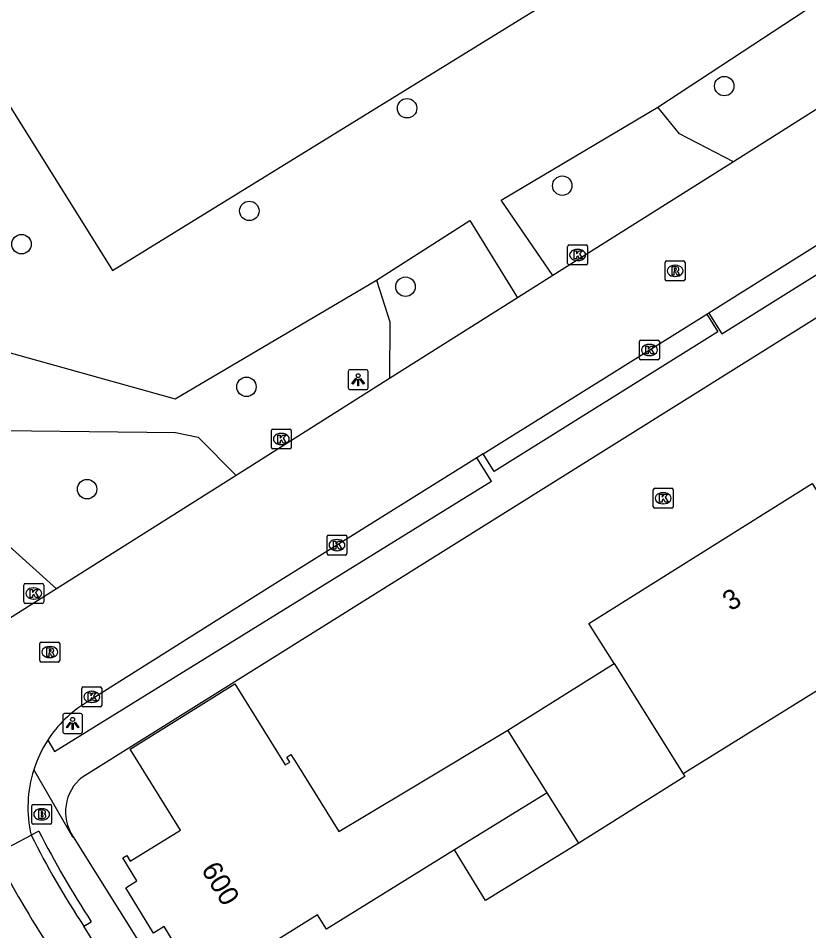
# Model space of a CAD drawing. Extents: x 159353 to 160616, y 385893 to 387321.
# Drawn here: x 159551.4 to 159591.13, y 386083.54 to 386129.36 of the extents above; entities that cross this region are included whole.
import ezdxf

# ---------------------------------------------------------------- set-up
doc = ezdxf.new("R2010")
doc.units = 0
for name, color, linetype in [('IMGEO_Berm_groen', 7, 'Continuous'), ('IMGEO_Boom', 7, 'Continuous'), ('IMGEO_Brandkraan', 7, 'Continuous'), ('IMGEO_Fietspad_gesloten', 7, 'Continuous'), ('IMGEO_Groenvoorziening', 7, 'Continuous'), ('IMGEO_Kolk', 7, 'Continuous'), ('IMGEO_Lichtpunt', 7, 'Continuous'), ('IMGEO_Pand', 7, 'Continuous'), ('IMGEO_Pand_nummerreeks', 7, 'Continuous'), ('IMGEO_Rijbaan_lokaal_open', 7, 'Continuous'), ('IMGEO_Rioolput', 7, 'Continuous'), ('IMGEO_Voetpad_open', 7, 'Continuous')]:
    doc.layers.add(name, color=color, linetype=linetype)

msp = doc.modelspace()

# ---------------------------------------------------------------- linework, layer by layer
at = {"layer": 'IMGEO_Berm_groen'}
msp.add_lwpolyline([(159549.247, 386105.516), (159550.241, 386103.468), (159553.325, 386100.716)], dxfattribs=at)
at = {"layer": 'IMGEO_Boom'}
for centre in [(159586.882, 386125.954), (159570.943, 386124.84), (159578.739, 386120.953), (159563.014, 386119.686), (159551.565, 386118.016), (159570.862, 386115.878), (159562.87, 386110.85), (159554.86, 386105.713)]:
    msp.add_circle(centre, 0.489, dxfattribs=at)
at = {"layer": 'IMGEO_Brandkraan'}
for p, q in [((159552.152, 386089.886), (159553.004, 386089.886)), ((159552.077, 386088.96), (159552.077, 386089.812)), ((159552.565, 386089.666), (159552.59, 386089.666)), ((159553.078, 386089.812), (159553.078, 386088.96)), ((159552.588, 386089.106), (159552.563, 386089.106)), ((159553.004, 386088.886), (159552.152, 386088.886))]:
    msp.add_line(p, q, dxfattribs=at)
for points in [[(159552.152, 386089.886), (159553.004, 386089.886)], [(159552.077, 386088.96), (159552.077, 386089.812)], [(159552.425, 386089.586), (159552.425, 386089.186), (159552.638, 386089.186)], [(159552.656, 386089.586), (159552.425, 386089.586)], [(159552.604, 386089.505), (159552.55, 386089.505), (159552.55, 386089.429)], [(159552.55, 386089.429), (159552.603, 386089.429)], [(159553.078, 386089.812), (159553.078, 386088.96)], [(159552.612, 386089.353), (159552.55, 386089.353), (159552.55, 386089.272)], [(159552.55, 386089.272), (159552.612, 386089.272)], [(159553.004, 386088.886), (159552.152, 386088.886)]]:
    msp.add_lwpolyline(points, dxfattribs=at)
for centre, radius, start, end in [((159552.154, 386089.81), 0.0765, 91.552, 178.448), ((159552.154, 386089.81), 0.0765, 91.552, 178.448), ((159553.002, 386089.81), 0.0765, 1.552, 88.448), ((159553.002, 386089.81), 0.0765, 1.552, 88.448), ((159552.605, 386089.467), 0.0379, 267.8285, 90.9355), ((159552.66, 386089.441), 0.145, 59.4692, 91.5367), ((159552.685, 386089.488), 0.0922, 285.5137, 58.1501), ((159552.154, 386088.962), 0.0765, 181.552, 268.448), ((159552.154, 386088.962), 0.0765, 181.552, 268.448), ((159552.613, 386089.312), 0.0404, 269.8759, 90.5077), ((159552.644, 386089.437), 0.251, 268.6676, 293.5347), ((159552.69, 386089.296), 0.105, 301.3115, 78.989), ((159553.002, 386088.962), 0.0765, 271.552, 358.448), ((159553.002, 386088.962), 0.0765, 271.552, 358.448)]:
    msp.add_arc(centre, radius, start, end, dxfattribs=at)
for centre, major_axis, ratio, start_param, end_param in [((159552.564, 386089.386), (-0.387, 0.002), 0.722429, 4.712389, 7.853982), ((159552.589, 386089.386), (-0.39, 0.002), 0.717154, 1.570796, 4.712389)]:
    msp.add_ellipse(centre, major_axis=major_axis, ratio=ratio, start_param=start_param, end_param=end_param, dxfattribs=at)
at = {"layer": 'IMGEO_Fietspad_gesloten'}
msp.add_arc((159589.601, 386107.064), 43.982, 206.5663, 213.7628, dxfattribs=at)
at = {"layer": 'IMGEO_Groenvoorziening'}
for points in [[(159537.348, 386146.745), (159556.131, 386116.691), (159602.836, 386145.461)], [(159583.541, 386124.895), (159593.579, 386131.485)], [(159578.275, 386116.439), (159575.67, 386120.226), (159583.541, 386124.895)], [(159587.35, 386122.158), (159584.628, 386123.562), (159583.541, 386124.895)], [(159542.791, 386124.554), (159549.37, 386113.143), (159549.723, 386112.907), (159559.291, 386110.25), (159569.411, 386116.215)], [(159569.411, 386116.215), (159574.089, 386119.197), (159576.494, 386115.317)], [(159569.411, 386116.215), (159570.08, 386114.109), (159570.062, 386111.264)], [(159547.706, 386108.69), (159559.298, 386108.563), (159560.446, 386108.325), (159562.354, 386106.406)]]:
    msp.add_lwpolyline(points, dxfattribs=at)
at = {"layer": 'IMGEO_Kolk'}
for p, q in [((159579.012, 386117.048), (159579.012, 386117.9)), ((159579.087, 386117.974), (159579.939, 386117.974)), ((159580.013, 386117.9), (159580.013, 386117.048)), ((159579.5, 386117.754), (159579.525, 386117.754)), ((159579.939, 386116.974), (159579.087, 386116.974)), ((159579.523, 386117.194), (159579.498, 386117.194)), ((159582.62, 386112.275), (159582.62, 386113.127)), ((159582.695, 386113.201), (159583.547, 386113.201)), ((159583.108, 386112.981), (159583.133, 386112.981)), ((159583.621, 386113.127), (159583.621, 386112.275)), ((159583.131, 386112.421), (159583.106, 386112.421)), ((159583.547, 386112.201), (159582.695, 386112.201)), ((159564.121, 386107.805), (159564.121, 386108.657)), ((159564.196, 386108.731), (159565.048, 386108.731)), ((159565.122, 386108.657), (159565.122, 386107.805)), ((159564.609, 386108.511), (159564.634, 386108.511)), ((159565.048, 386107.731), (159564.196, 386107.731)), ((159564.632, 386107.951), (159564.607, 386107.951)), ((159583.312, 386104.83), (159583.312, 386105.682)), ((159583.387, 386105.756), (159584.239, 386105.756)), ((159583.8, 386105.536), (159583.825, 386105.536)), ((159584.313, 386105.682), (159584.313, 386104.83)), ((159584.239, 386104.756), (159583.387, 386104.756)), ((159583.823, 386104.976), (159583.798, 386104.976)), ((159566.919, 386102.477), (159566.919, 386103.329)), ((159566.994, 386103.403), (159567.846, 386103.403)), ((159567.407, 386103.183), (159567.432, 386103.183)), ((159567.92, 386103.329), (159567.92, 386102.477)), ((159567.846, 386102.403), (159566.994, 386102.403)), ((159567.43, 386102.623), (159567.405, 386102.623)), ((159551.679, 386100.048), (159551.679, 386100.9)), ((159551.754, 386100.974), (159552.606, 386100.974)), ((159552.68, 386100.9), (159552.68, 386100.048)), ((159552.167, 386100.754), (159552.192, 386100.754)), ((159552.606, 386099.974), (159551.754, 386099.974)), ((159552.19, 386100.194), (159552.165, 386100.194)), ((159554.597, 386094.856), (159554.597, 386095.708)), ((159554.672, 386095.782), (159555.524, 386095.782)), ((159555.085, 386095.562), (159555.11, 386095.562)), ((159555.598, 386095.708), (159555.598, 386094.856)), ((159555.108, 386095.002), (159555.083, 386095.002)), ((159555.524, 386094.782), (159554.672, 386094.782))]:
    msp.add_line(p, q, dxfattribs=at)
for points in [[(159579.012, 386117.048), (159579.012, 386117.9)], [(159579.087, 386117.974), (159579.939, 386117.974)], [(159580.013, 386117.9), (159580.013, 386117.048)], [(159579.333, 386117.674), (159579.456, 386117.674), (159579.456, 386117.523), (159579.586, 386117.674), (159579.75, 386117.674), (159579.604, 386117.523), (159579.757, 386117.274), (159579.605, 386117.274), (159579.52, 386117.438), (159579.456, 386117.371), (159579.456, 386117.274), (159579.333, 386117.274), (159579.333, 386117.674)], [(159579.939, 386116.974), (159579.087, 386116.974)], [(159582.62, 386112.275), (159582.62, 386113.127)], [(159582.695, 386113.201), (159583.547, 386113.201)], [(159582.941, 386112.901), (159583.064, 386112.901), (159583.064, 386112.75), (159583.194, 386112.901), (159583.358, 386112.901), (159583.212, 386112.75), (159583.365, 386112.501), (159583.213, 386112.501), (159583.128, 386112.665), (159583.064, 386112.598), (159583.064, 386112.501), (159582.941, 386112.501), (159582.941, 386112.901)], [(159583.621, 386113.127), (159583.621, 386112.275)], [(159583.547, 386112.201), (159582.695, 386112.201)], [(159564.121, 386107.805), (159564.121, 386108.657)], [(159564.196, 386108.731), (159565.048, 386108.731)], [(159565.122, 386108.657), (159565.122, 386107.805)], [(159564.442, 386108.431), (159564.565, 386108.431), (159564.565, 386108.28), (159564.695, 386108.431), (159564.859, 386108.431), (159564.713, 386108.28), (159564.866, 386108.031), (159564.714, 386108.031), (159564.629, 386108.195), (159564.565, 386108.128), (159564.565, 386108.031), (159564.442, 386108.031), (159564.442, 386108.431)], [(159565.048, 386107.731), (159564.196, 386107.731)], [(159583.312, 386104.83), (159583.312, 386105.682)], [(159583.387, 386105.756), (159584.239, 386105.756)], [(159583.633, 386105.456), (159583.756, 386105.456), (159583.756, 386105.305), (159583.886, 386105.456), (159584.05, 386105.456), (159583.904, 386105.305), (159584.057, 386105.056), (159583.905, 386105.056), (159583.82, 386105.22), (159583.756, 386105.153), (159583.756, 386105.056), (159583.633, 386105.056), (159583.633, 386105.456)], [(159584.313, 386105.682), (159584.313, 386104.83)], [(159584.239, 386104.756), (159583.387, 386104.756)], [(159566.919, 386102.477), (159566.919, 386103.329)], [(159566.994, 386103.403), (159567.846, 386103.403)], [(159567.92, 386103.329), (159567.92, 386102.477)], [(159567.24, 386103.103), (159567.363, 386103.103), (159567.363, 386102.952), (159567.493, 386103.103), (159567.657, 386103.103), (159567.511, 386102.952), (159567.664, 386102.703), (159567.512, 386102.703), (159567.427, 386102.867), (159567.363, 386102.8), (159567.363, 386102.703), (159567.24, 386102.703), (159567.24, 386103.103)], [(159567.846, 386102.403), (159566.994, 386102.403)], [(159551.679, 386100.048), (159551.679, 386100.9)], [(159551.754, 386100.974), (159552.606, 386100.974)], [(159552.68, 386100.9), (159552.68, 386100.048)], [(159552, 386100.674), (159552.123, 386100.674), (159552.123, 386100.523), (159552.253, 386100.674), (159552.417, 386100.674), (159552.271, 386100.523), (159552.424, 386100.274), (159552.272, 386100.274), (159552.187, 386100.438), (159552.123, 386100.371), (159552.123, 386100.274), (159552, 386100.274), (159552, 386100.674)], [(159552.606, 386099.974), (159551.754, 386099.974)], [(159554.597, 386094.856), (159554.597, 386095.708)], [(159554.672, 386095.782), (159555.524, 386095.782)], [(159554.918, 386095.482), (159555.041, 386095.482), (159555.041, 386095.331), (159555.171, 386095.482), (159555.335, 386095.482), (159555.189, 386095.331), (159555.342, 386095.082), (159555.19, 386095.082), (159555.105, 386095.246), (159555.041, 386095.179), (159555.041, 386095.082), (159554.918, 386095.082), (159554.918, 386095.482)], [(159555.598, 386095.708), (159555.598, 386094.856)], [(159555.524, 386094.782), (159554.672, 386094.782)]]:
    msp.add_lwpolyline(points, dxfattribs=at)
for centre, start, end in [((159579.089, 386117.898), 91.552, 178.448), ((159579.089, 386117.898), 91.552, 178.448), ((159579.937, 386117.898), 1.552, 88.448), ((159579.937, 386117.898), 1.552, 88.448), ((159579.089, 386117.05), 181.552, 268.448), ((159579.089, 386117.05), 181.552, 268.448), ((159579.937, 386117.05), 271.552, 358.448), ((159579.937, 386117.05), 271.552, 358.448), ((159582.697, 386113.125), 91.552, 178.448), ((159582.697, 386113.125), 91.552, 178.448), ((159583.545, 386113.125), 1.552, 88.448), ((159583.545, 386113.125), 1.552, 88.448), ((159582.697, 386112.277), 181.552, 268.448), ((159582.697, 386112.277), 181.552, 268.448), ((159583.545, 386112.277), 271.552, 358.448), ((159583.545, 386112.277), 271.552, 358.448), ((159564.198, 386108.655), 91.552, 178.448), ((159564.198, 386108.655), 91.552, 178.448), ((159565.046, 386108.655), 1.552, 88.448), ((159565.046, 386108.655), 1.552, 88.448), ((159564.198, 386107.807), 181.552, 268.448), ((159564.198, 386107.807), 181.552, 268.448), ((159565.046, 386107.807), 271.552, 358.448), ((159565.046, 386107.807), 271.552, 358.448), ((159583.389, 386105.68), 91.552, 178.448), ((159583.389, 386105.68), 91.552, 178.448), ((159584.237, 386105.68), 1.552, 88.448), ((159584.237, 386105.68), 1.552, 88.448), ((159583.389, 386104.832), 181.552, 268.448), ((159583.389, 386104.832), 181.552, 268.448), ((159584.237, 386104.832), 271.552, 358.448), ((159584.237, 386104.832), 271.552, 358.448), ((159566.996, 386103.327), 91.552, 178.448), ((159566.996, 386103.327), 91.552, 178.448), ((159567.844, 386103.327), 1.552, 88.448), ((159567.844, 386103.327), 1.552, 88.448), ((159566.996, 386102.479), 181.552, 268.448), ((159566.996, 386102.479), 181.552, 268.448), ((159567.844, 386102.479), 271.552, 358.448), ((159567.844, 386102.479), 271.552, 358.448), ((159551.756, 386100.898), 91.552, 178.448), ((159551.756, 386100.898), 91.552, 178.448), ((159552.604, 386100.898), 1.552, 88.448), ((159552.604, 386100.898), 1.552, 88.448), ((159551.756, 386100.05), 181.552, 268.448), ((159551.756, 386100.05), 181.552, 268.448), ((159552.604, 386100.05), 271.552, 358.448), ((159552.604, 386100.05), 271.552, 358.448), ((159554.674, 386095.706), 91.552, 178.448), ((159554.674, 386095.706), 91.552, 178.448), ((159555.522, 386095.706), 1.552, 88.448), ((159555.522, 386095.706), 1.552, 88.448), ((159554.674, 386094.858), 181.552, 268.448), ((159554.674, 386094.858), 181.552, 268.448), ((159555.522, 386094.858), 271.552, 358.448), ((159555.522, 386094.858), 271.552, 358.448)]:
    msp.add_arc(centre, 0.0765, start, end, dxfattribs=at)
for centre, major_axis, ratio, start_param, end_param in [((159579.499, 386117.474), (-0.387, 0.002), 0.722429, 4.712389, 7.853982), ((159579.524, 386117.474), (-0.39, 0.002), 0.717154, 1.570796, 4.712389), ((159583.107, 386112.701), (-0.387, 0.002), 0.722429, 4.712389, 7.853982), ((159583.132, 386112.701), (-0.39, 0.002), 0.717154, 1.570796, 4.712389), ((159564.608, 386108.231), (-0.387, 0.002), 0.722429, 4.712389, 7.853982), ((159564.633, 386108.231), (-0.39, 0.002), 0.717154, 1.570796, 4.712389), ((159583.799, 386105.256), (-0.387, 0.002), 0.722429, 4.712389, 7.853982), ((159583.824, 386105.256), (-0.39, 0.002), 0.717154, 1.570796, 4.712389), ((159567.406, 386102.903), (-0.387, 0.002), 0.722429, 4.712389, 7.853982), ((159567.431, 386102.903), (-0.39, 0.002), 0.717154, 1.570796, 4.712389), ((159552.166, 386100.474), (-0.387, 0.002), 0.722429, 4.712389, 7.853982), ((159552.191, 386100.474), (-0.39, 0.002), 0.717154, 1.570796, 4.712389), ((159555.084, 386095.282), (-0.387, 0.002), 0.722429, 4.712389, 7.853982), ((159555.109, 386095.282), (-0.39, 0.002), 0.717154, 1.570796, 4.712389)]:
    msp.add_ellipse(centre, major_axis=major_axis, ratio=ratio, start_param=start_param, end_param=end_param, dxfattribs=at)
at = {"layer": 'IMGEO_Lichtpunt'}
for p, q in [((159567.985, 386111.615), (159567.985, 386110.808)), ((159567.985, 386111.615), (159567.985, 386110.808)), ((159568.887, 386111.71), (159568.079, 386111.71)), ((159568.887, 386111.71), (159568.079, 386111.71)), ((159568.981, 386110.808), (159568.981, 386111.615)), ((159568.981, 386110.808), (159568.981, 386111.615)), ((159568.079, 386110.714), (159568.887, 386110.714)), ((159568.079, 386110.714), (159568.887, 386110.714)), ((159554.537, 386094.447), (159553.729, 386094.447)), ((159554.537, 386094.447), (159553.729, 386094.447)), ((159553.635, 386094.352), (159553.635, 386093.545)), ((159553.635, 386094.352), (159553.635, 386093.545)), ((159554.631, 386093.545), (159554.631, 386094.352)), ((159554.631, 386093.545), (159554.631, 386094.352)), ((159553.729, 386093.451), (159554.537, 386093.451)), ((159553.729, 386093.451), (159554.537, 386093.451))]:
    msp.add_line(p, q, dxfattribs=at)
for points in [[(159568.359, 386111.279), (159568.398, 386111.251), (159568.21, 386110.989), (159568.172, 386111.016), (159568.359, 386111.279)], [(159568.461, 386111.231), (159568.508, 386111.231), (159568.508, 386110.909), (159568.461, 386110.909), (159568.461, 386111.231)], [(159568.571, 386111.251), (159568.609, 386111.278), (159568.796, 386111.016), (159568.757, 386110.988), (159568.571, 386111.251)], [(159554.009, 386094.016), (159554.048, 386093.988), (159553.86, 386093.726), (159553.822, 386093.753), (159554.009, 386094.016)], [(159554.221, 386093.988), (159554.259, 386094.015), (159554.446, 386093.753), (159554.407, 386093.725), (159554.221, 386093.988)], [(159554.111, 386093.968), (159554.158, 386093.968), (159554.158, 386093.646), (159554.111, 386093.646), (159554.111, 386093.968)]]:
    msp.add_lwpolyline(points, dxfattribs=at)
for centre in [(159568.484, 386111.413), (159554.134, 386094.15)]:
    msp.add_circle(centre, 0.0994, dxfattribs=at)
for centre, start, end in [((159568.079, 386111.615), 90, 180), ((159568.079, 386111.615), 90, 180), ((159568.887, 386111.615), 0, 90), ((159568.887, 386111.615), 0, 90), ((159568.079, 386110.808), 180, 270), ((159568.079, 386110.808), 180, 270), ((159568.887, 386110.808), 270, 0), ((159568.887, 386110.808), 270, 360), ((159553.729, 386094.352), 90, 180), ((159553.729, 386094.352), 90, 180), ((159554.537, 386094.352), 0, 90), ((159554.537, 386094.352), 0, 90), ((159553.729, 386093.545), 180, 270), ((159553.729, 386093.545), 180, 270), ((159554.537, 386093.545), 270, 0), ((159554.537, 386093.545), 270, 360)]:
    msp.add_arc(centre, 0.0946, start, end, dxfattribs=at)
at = {"layer": 'IMGEO_Pand'}
for points in [[(159581.343, 386096.96), (159580.084, 386098.965), (159591.298, 386106.003), (159593.34, 386102.751)], [(159596.069, 386098.394), (159584.819, 386091.42)], [(159576.006, 386093.612), (159581.343, 386096.96)], [(159581.343, 386096.96), (159584.819, 386091.42)], [(159560.753, 386080.458), (159558.735, 386083.748), (159558.202, 386083.421), (159556.805, 386085.699), (159557.369, 386086.045), (159556.661, 386087.199), (159556.852, 386087.316), (159557.03, 386087.026), (159559.553, 386088.593), (159557.025, 386092.662), (159562.291, 386095.934), (159564.819, 386091.865), (159565.053, 386092.01), (159564.896, 386092.263), (159565.104, 386092.394), (159565.396, 386091.924), (159567.513, 386088.515), (159568.806, 386089.291), (159571.353, 386090.819), (159576.006, 386093.612)], [(159577.978, 386090.469), (159576.006, 386093.612)], [(159584.819, 386091.42), (159584.904, 386091.285), (159579.567, 386087.936)], [(159577.978, 386090.469), (159573.319, 386087.602)], [(159579.567, 386087.936), (159577.978, 386090.469)], [(159573.319, 386087.602), (159566.89, 386083.612), (159566.444, 386084.33), (159560.772, 386080.81)], [(159579.567, 386087.936), (159574.879, 386085.06), (159573.319, 386087.602)]]:
    msp.add_lwpolyline(points, dxfattribs=at)
at = {"layer": 'IMGEO_Rijbaan_lokaal_open'}
for points in [[(159609.613, 386129.277), (159586.1, 386114.559)], [(159595.055, 386127.013), (159587.35, 386122.158)], [(159587.35, 386122.158), (159578.275, 386116.439)], [(159578.275, 386116.439), (159576.494, 386115.317)], [(159576.494, 386115.317), (159570.062, 386111.264)], [(159574.766, 386107.488), (159586.005, 386114.499)], [(159586.1, 386114.559), (159586.005, 386114.499)], [(159570.062, 386111.264), (159562.354, 386106.406)], [(159574.455, 386107.294), (159563.923, 386100.723), (159554.83, 386095)], [(159574.766, 386107.488), (159574.455, 386107.294)], [(159562.354, 386106.406), (159553.325, 386100.716)], [(159553.325, 386100.716), (159549.67, 386098.413)], [(159550.263, 386087.394), (159552.05, 386088.344)]]:
    msp.add_lwpolyline(points, dxfattribs=at)
for centre, radius, start, end in [((159558.056, 386089.737), 6.173, 121.5114, 146.9378), ((159558.042, 386089.755), 6.151, 147.0027, 162.3613), ((159558.044, 386089.746), 6.155, 162.2864, 193.1673)]:
    msp.add_arc(centre, radius, start, end, dxfattribs=at)
at = {"layer": 'IMGEO_Rioolput'}
for p, q in [((159583.909, 386116.248), (159583.909, 386117.1)), ((159583.984, 386117.174), (159584.836, 386117.174)), ((159584.397, 386116.954), (159584.422, 386116.954)), ((159584.91, 386117.1), (159584.91, 386116.248)), ((159584.836, 386116.174), (159583.984, 386116.174)), ((159584.42, 386116.394), (159584.395, 386116.394)), ((159552.486, 386097.107), (159552.486, 386097.959)), ((159552.561, 386098.033), (159553.413, 386098.033)), ((159552.974, 386097.813), (159552.999, 386097.813)), ((159553.487, 386097.959), (159553.487, 386097.107)), ((159552.997, 386097.253), (159552.972, 386097.253)), ((159553.413, 386097.033), (159552.561, 386097.033))]:
    msp.add_line(p, q, dxfattribs=at)
for points in [[(159583.909, 386116.248), (159583.909, 386117.1)], [(159583.984, 386117.174), (159584.836, 386117.174)], [(159584.91, 386117.1), (159584.91, 386116.248)], [(159584.498, 386116.872), (159584.246, 386116.874), (159584.246, 386116.474)], [(159584.246, 386116.474), (159584.37, 386116.474), (159584.37, 386116.636), (159584.381, 386116.636)], [(159584.424, 386116.793), (159584.37, 386116.793), (159584.37, 386116.712)], [(159584.37, 386116.712), (159584.422, 386116.712)], [(159584.428, 386116.607), (159584.499, 386116.474), (159584.639, 386116.474), (159584.574, 386116.6)], [(159584.836, 386116.174), (159583.984, 386116.174)], [(159552.486, 386097.107), (159552.486, 386097.959)], [(159552.561, 386098.033), (159553.413, 386098.033)], [(159553.075, 386097.731), (159552.823, 386097.733), (159552.823, 386097.333)], [(159553.001, 386097.652), (159552.947, 386097.652), (159552.947, 386097.571)], [(159553.487, 386097.959), (159553.487, 386097.107)], [(159552.823, 386097.333), (159552.947, 386097.333), (159552.947, 386097.495), (159552.958, 386097.495)], [(159552.947, 386097.571), (159552.999, 386097.571)], [(159553.005, 386097.466), (159553.076, 386097.333), (159553.216, 386097.333), (159553.151, 386097.459)], [(159553.413, 386097.033), (159552.561, 386097.033)]]:
    msp.add_lwpolyline(points, dxfattribs=at)
for centre, radius, start, end in [((159583.986, 386117.098), 0.0765, 91.552, 178.448), ((159583.986, 386117.098), 0.0765, 91.552, 178.448), ((159584.834, 386117.098), 0.0765, 1.552, 88.448), ((159584.834, 386117.098), 0.0765, 1.552, 88.448), ((159584.38, 386116.583), 0.0533, 26.0293, 88.6989), ((159584.406, 386116.901), 0.19, 274.7715, 282.9687), ((159584.43, 386116.697), 0.0964, 77.0061, 93.1865), ((159584.444, 386116.754), 0.0378, 276.6634, 79.6772), ((159584.497, 386116.762), 0.109, 350.3612, 89.416), ((159584.495, 386116.762), 0.112, 277.5842, 350.9817), ((159584.479, 386116.547), 0.108, 29.5134, 73.7905), ((159583.986, 386116.25), 0.0765, 181.552, 268.448), ((159583.986, 386116.25), 0.0765, 181.552, 268.448), ((159584.834, 386116.25), 0.0765, 271.552, 358.448), ((159584.834, 386116.25), 0.0765, 271.552, 358.448), ((159552.563, 386097.957), 0.0765, 91.552, 178.448), ((159552.563, 386097.957), 0.0765, 91.552, 178.448), ((159553.007, 386097.556), 0.0964, 77.0061, 93.1865), ((159553.021, 386097.613), 0.0378, 276.6634, 79.6772), ((159553.074, 386097.621), 0.109, 350.3612, 89.416), ((159553.411, 386097.957), 0.0765, 1.552, 88.448), ((159553.411, 386097.957), 0.0765, 1.552, 88.448), ((159552.957, 386097.442), 0.0533, 26.0293, 88.6989), ((159552.983, 386097.76), 0.19, 274.7715, 282.9687), ((159553.072, 386097.621), 0.112, 277.5842, 350.9817), ((159553.056, 386097.406), 0.108, 29.5134, 73.7905), ((159552.563, 386097.109), 0.0765, 181.552, 268.448), ((159552.563, 386097.109), 0.0765, 181.552, 268.448), ((159553.411, 386097.109), 0.0765, 271.552, 358.448), ((159553.411, 386097.109), 0.0765, 271.552, 358.448)]:
    msp.add_arc(centre, radius, start, end, dxfattribs=at)
for centre, major_axis, ratio, start_param, end_param in [((159584.396, 386116.674), (-0.387, 0.002), 0.722429, 4.712389, 7.853982), ((159584.421, 386116.674), (-0.39, 0.002), 0.717154, 1.570796, 4.712389), ((159552.973, 386097.533), (-0.387, 0.002), 0.722429, 4.712389, 7.853982), ((159552.998, 386097.533), (-0.39, 0.002), 0.717154, 1.570796, 4.712389)]:
    msp.add_ellipse(centre, major_axis=major_axis, ratio=ratio, start_param=start_param, end_param=end_param, dxfattribs=at)
at = {"layer": 'IMGEO_Voetpad_open'}
for points in [[(159586.1, 386114.559), (159586.766, 386113.506), (159610.295, 386128.213), (159609.613, 386129.277)], [(159614.607, 386128.752), (159587.619, 386111.878), (159554.627, 386091.25)], [(159586.005, 386114.499), (159586.555, 386113.617), (159575.316, 386106.606), (159574.766, 386107.488)], [(159552.883, 386093.105), (159553.215, 386092.54), (159575.185, 386106.122), (159574.455, 386107.294)], [(159552.18, 386091.619), (159554.126, 386088.263), (159554.162, 386088.263)], [(159552.438, 386088.544), (159552.05, 386088.344)], [(159554.162, 386088.263), (159585.478, 386038.285), (159618.566, 385984.984), (159617.942, 385984.608), (159619.588, 385981.954), (159622.47, 385977.308), (159627.126, 385969.959), (159627.843, 385970.4), (159643.051, 385946.005), (159667.875, 385907.187)], [(159554.692, 386083.769), (159555.07, 386083.994)], [(159558.405, 386077.818), (159554.692, 386083.769)]]:
    msp.add_lwpolyline(points, dxfattribs=at)
for centre, radius, start, end in [((159555.977, 386089.51), 2.202, 127.8058, 214.4972), ((159596.763, 386111.148), 49.756, 207.0199, 213.0756), ((159591.756, 386108.223), 44.404, 206.5954, 213.4163)]:
    msp.add_arc(centre, radius, start, end, dxfattribs=at)

# ---------------------------------------------------------------- texts
at = {"layer": 'IMGEO_Pand_nummerreeks'}
for s, rotation, p in [('3', 32.1127, (159587.202, 386099.56)), ('600', 301.0438, (159560.569, 386086.616))]:
    msp.add_text(s, height=1, rotation=rotation, dxfattribs=at).set_placement(p)

doc.saveas('drawing.dxf')
